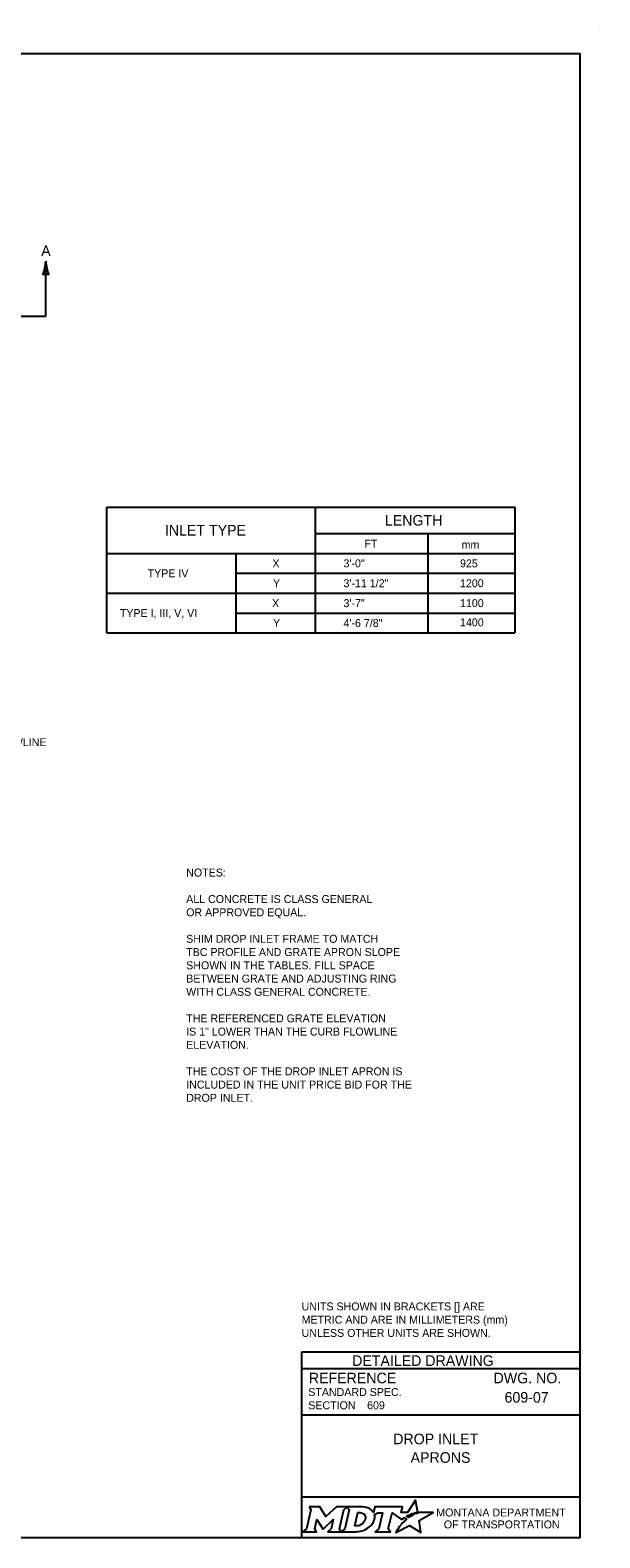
# Model space of a CAD drawing. Extents: x 49991.4 to 50048.3, y 49987.6 to 50018.3.
# Drawn here: x 50012.6 to 50016.9, y 49987.8 to 49999.18 of the extents above; entities that cross this region are included whole.
import ezdxf

# ---------------------------------------------------------------- set-up
doc = ezdxf.new("R2010")
doc.units = 0
for name, color, linetype in [('Default', 7, 'Continuous'), ('Level 1', 7, 'Continuous'), ('Level 2', 7, 'Continuous'), ('Level 5', 7, 'Continuous'), ('Level 6', 7, 'Continuous')]:
    doc.layers.add(name, color=color, linetype=linetype)

msp = doc.modelspace()

# ---------------------------------------------------------------- linework, layer by layer
at = {"layer": 'Default'}
for points in [[(50015.513, 49987.981), (50015.502, 49987.987), (50015.514, 49987.99), (50015.526, 49987.991), (50015.508, 49988.082), (50015.449, 49987.99), (50015.401, 49987.99), (50015.412, 49988.034), (50015.202, 49988.034), (50015.192, 49987.991), (50015.186, 49988)], [(50014.706, 49988.034), (50014.72, 49988.01), (50014.686, 49987.867), (50014.66, 49987.845), (50014.762, 49987.845), (50014.749, 49987.867), (50014.765, 49987.937), (50014.809, 49987.868), (50014.814, 49987.868), (50014.889, 49987.938), (50014.872, 49987.867), (50014.848, 49987.845), (50014.949, 49987.845), (50014.936, 49987.868), (50014.969, 49988.011)], [(50014.969, 49988.011), (50014.994, 49988.034), (50014.912, 49988.034), (50014.832, 49987.961), (50014.788, 49988.034), (50014.706, 49988.034)], [(50015.108, 49988.034), (50014.994, 49988.034), (50015.009, 49988.011), (50014.975, 49987.867), (50014.949, 49987.845), (50015.06, 49987.845)], [(50015.132, 49987.947), (50015.13, 49987.939), (50015.127, 49987.93), (50015.123, 49987.922), (50015.118, 49987.914), (50015.111, 49987.907), (50015.103, 49987.901), (50015.095, 49987.896), (50015.086, 49987.892), (50015.077, 49987.89), (50015.067, 49987.889), (50015.052, 49987.889), (50015.075, 49987.989), (50015.091, 49987.989), (50015.099, 49987.988), (50015.106, 49987.986), (50015.113, 49987.983), (50015.119, 49987.979), (50015.124, 49987.974), (50015.128, 49987.968), (50015.13, 49987.962), (50015.132, 49987.955), (50015.132, 49987.952), (50015.132, 49987.947)], [(50015.199, 49987.975), (50015.224, 49987.988), (50015.261, 49987.988), (50015.232, 49987.867), (50015.205, 49987.845), (50015.321, 49987.845), (50015.304, 49987.867), (50015.332, 49987.988), (50015.403, 49987.936), (50015.424, 49987.951), (50015.444, 49987.94)], [(50015.388, 49987.884), (50015.373, 49987.86), (50015.368, 49987.852), (50015.362, 49987.844), (50015.36, 49987.839), (50015.465, 49987.893), (50015.549, 49987.838), (50015.536, 49987.93), (50015.643, 49987.989), (50015.594, 49987.989), (50015.564, 49987.99), (50015.543, 49987.99), (50015.536, 49987.989), (50015.531, 49987.987), (50015.523, 49987.985), (50015.513, 49987.981)], [(50015.462, 49987.954), (50015.46, 49987.952), (50015.442, 49987.961), (50015.452, 49987.967), (50015.456, 49987.969), (50015.465, 49987.973), (50015.47, 49987.976), (50015.478, 49987.979), (50015.485, 49987.982), (50015.497, 49987.974), (50015.493, 49987.972), (50015.489, 49987.97), (50015.484, 49987.967), (50015.479, 49987.965), (50015.478, 49987.963), (50015.475, 49987.962), (50015.472, 49987.96), (50015.47, 49987.959), (50015.467, 49987.957), (50015.465, 49987.955), (50015.462, 49987.954)], [(50015.106, 49987.852), (50015.114, 49987.855), (50015.127, 49987.86), (50015.148, 49987.871)], [(50015.402, 49987.9), (50015.402, 49987.9)]]:
    msp.add_lwpolyline(points, dxfattribs=at)
for centre, radius, start, end in [((50015.087, 49987.973), 0.118, 300.9103, 339.1383), ((50015.131, 49987.955), 0.0709, 339.5329, 15.8582)]:
    msp.add_arc(centre, radius, start, end, dxfattribs=at)
for centre, major_axis, ratio, start_param, end_param in [((50015.106, 49987.986), (0.0834, -0.0037), 0.568097, 0.61298, 1.570796), ((50015.161, 49987.994), (0.0361, -0.0295), 0.469099, 1.225588, 1.570796), ((50015.433, 49987.93), (-0.0112, -0.0097), 0.021651, 3.157348, 6.283185), ((50015.06, 49987.993), (0, 0.148), 0.987302, 3.139398, 3.456847), ((50015.395, 49987.892), (-0.00694, -0.00806), 0.008222, 0, 3.137361), ((50015.412, 49987.911), (-0.0098, -0.0102), 0.016458, 3.141593, 6.279097)]:
    msp.add_ellipse(centre, major_axis=major_axis, ratio=ratio, start_param=start_param, end_param=end_param, dxfattribs=at)
at = {"layer": 'Level 1'}
msp.add_line((50016.9, 49999.176), (50016.9, 49999.176), dxfattribs=at)
msp.add_lwpolyline([(49999.384, 49998.999), (50016.75, 49998.999), (50016.75, 49987.799), (49999.384, 49987.799)], close=True, dxfattribs=at)
at = {"layer": 'Level 2'}
for p, q in [((50013.18, 49994.627), (50013.18, 49995.577)), ((50013.18, 49995.577), (50016.258, 49995.577)), ((50014.754, 49994.627), (50014.754, 49995.577)), ((50016.258, 49995.577), (50016.258, 49994.627)), ((50014.754, 49995.377), (50016.258, 49995.377)), ((50015.602, 49995.377), (50015.602, 49994.627)), ((50013.18, 49995.227), (50016.258, 49995.227)), ((50014.156, 49994.627), (50014.156, 49995.227)), ((50014.156, 49995.077), (50016.258, 49995.077)), ((50013.18, 49994.927), (50016.258, 49994.927)), ((50014.156, 49994.777), (50016.258, 49994.777)), ((50013.18, 49994.627), (50016.258, 49994.627))]:
    msp.add_line(p, q, dxfattribs=at)
at = {"layer": 'Level 5'}
for p, q in [((50016.75, 49989.199), (50014.65, 49989.199)), ((50014.65, 49989.199), (50014.65, 49987.799)), ((50016.75, 49989.074), (50014.65, 49989.074)), ((50016.386, 49988.859), (50016.386, 49988.859)), ((50016.75, 49988.724), (50014.65, 49988.724)), ((50015.144, 49988.799), (50015.144, 49988.799)), ((50015.7, 49988.475), (50015.7, 49988.475)), ((50016.75, 49988.106), (50014.65, 49988.106))]:
    msp.add_line(p, q, dxfattribs=at)
at = {"layer": 'Level 6'}
for q in [(50012.719, 49997.431), (50012.309, 49997.014)]:
    msp.add_line((50012.719, 49997.014), q, dxfattribs=at)
for centre, radius, start, end in [((50012.423, 49997.443), 0.296, 337.456, 357.6395), ((50013.03, 49997.447), 0.311, 182.8273, 202.0772), ((50012.719, 49997.26), 0.073, 72.1388, 107.8612)]:
    msp.add_arc(centre, radius, start, end, dxfattribs=at)

# ---------------------------------------------------------------- texts
at = {"layer": 'Default'}
for s, p in [('MONTANA DEPARTMENT', (50015.666, 49987.96)), ('OF TRANSPORTATION', (50015.723, 49987.87))]:
    msp.add_text(s, height=0.06, dxfattribs=at).set_placement(p)
at = {"layer": 'Level 2'}
for s, height, p in [('A', 0.08, (50012.685, 49997.471)), ('INLET TYPE', 0.08, (50013.618, 49995.362)), ('LENGTH', 0.08, (50015.278, 49995.437)), ('FT', 0.06, (50015.123, 49995.271)), ('mm', 0.06, (50015.857, 49995.263)), ('TYPE IV', 0.06, (50013.488, 49995.047)), ('X', 0.06, (50014.43, 49995.122)), ('3\'-0"', 0.06, (50014.966, 49995.122)), ('925', 0.06, (50015.845, 49995.122)), ('Y', 0.06, (50014.434, 49994.972)), ('3\'-11 1/2"', 0.06, (50014.966, 49994.972)), ('1200', 0.06, (50015.845, 49994.972)), ('X', 0.06, (50014.427, 49994.822)), ('3\'-7"', 0.06, (50014.966, 49994.822)), ('1100', 0.06, (50015.845, 49994.822)), ('TYPE I, III, V, VI', 0.06, (50013.278, 49994.747)), ('Y', 0.06, (50014.434, 49994.672)), ('4\'-6 7/8"', 0.06, (50014.966, 49994.672)), ('1400', 0.06, (50015.845, 49994.677)), ('CURB FLOWLINE', 0.06, (50012.065, 49993.773)), ('NOTES:', 0.06, (50013.779, 49992.789)), ('ALL CONCRETE IS CLASS GENERAL', 0.06, (50013.779, 49992.589)), ('OR APPROVED EQUAL.', 0.06, (50013.779, 49992.489)), ('TBC PROFILE AND GRATE APRON SLOPE', 0.06, (50013.779, 49992.189)), ('SHIM DROP INLET FRAME TO MATCH', 0.06, (50013.779, 49992.289)), ('SHOWN IN THE TABLES. FILL SPACE', 0.06, (50013.779, 49992.089)), ('BETWEEN GRATE AND ADJUSTING RING', 0.06, (50013.779, 49991.989)), ('WITH CLASS GENERAL CONCRETE.', 0.06, (50013.779, 49991.889)), ('THE REFERENCED GRATE ELEVATION', 0.06, (50013.779, 49991.689)), ('IS 1" LOWER THAN THE CURB FLOWLINE', 0.06, (50013.779, 49991.589)), ('ELEVATION.', 0.06, (50013.779, 49991.489)), ('THE COST OF THE DROP INLET APRON IS', 0.06, (50013.779, 49991.289)), ('INCLUDED IN THE UNIT PRICE BID FOR THE', 0.06, (50013.779, 49991.189)), ('DROP INLET.', 0.06, (50013.779, 49991.089)), ('UNITS SHOWN IN BRACKETS [] ARE', 0.06, (50014.65, 49989.515)), ('METRIC AND ARE IN MILLIMETERS (mm)', 0.06, (50014.65, 49989.415)), ('UNLESS OTHER UNITS ARE SHOWN.', 0.06, (50014.65, 49989.315)), ('609-07', 0.08, (50016.181, 49988.819)), ('609', 0.06, (50015.144, 49988.769)), ('DROP INLET', 0.08, (50015.341, 49988.505)), ('APRONS', 0.08, (50015.472, 49988.365))]:
    msp.add_text(s, height=height, dxfattribs=at).set_placement(p)
at = {"layer": 'Level 5'}
for s, height, p in [('DETAILED DRAWING', 0.0799, (50015.031, 49989.096)), ('REFERENCE', 0.08, (50014.704, 49988.965)), ('DWG. NO.', 0.08, (50016.098, 49988.965)), ('STANDARD SPEC.', 0.06, (50014.7, 49988.869)), ('SECTION', 0.06, (50014.7, 49988.769))]:
    msp.add_text(s, height=height, dxfattribs=at).set_placement(p)

doc.saveas('drawing.dxf')
